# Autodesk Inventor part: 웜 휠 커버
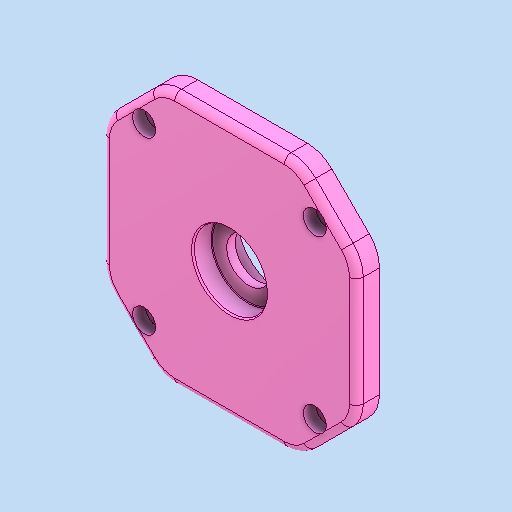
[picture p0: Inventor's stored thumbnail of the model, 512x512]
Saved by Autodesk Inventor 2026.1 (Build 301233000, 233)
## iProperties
Created: 2026-01
Part Number: 웜 휠 커버
Material: 알루미늄 6061
Document SubType Name: Modeling
Designer: PC-30
Density: 2.7 g/cm^3
Appearance: 기본값
Author: jhkim
Sending System: Autodesk Inventor 2026
Preprocessor: ST-DEVELOPER v20.1
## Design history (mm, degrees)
feature "솔리드1"
node "솔리드2"
